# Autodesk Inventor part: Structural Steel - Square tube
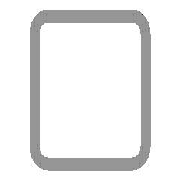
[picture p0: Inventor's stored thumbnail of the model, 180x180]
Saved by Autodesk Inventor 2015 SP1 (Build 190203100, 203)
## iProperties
_CCFamilyMember: 2
_CCFamilyDisplayName: ISO 4019 (Square) - Structural steels - Cold-formed, welded, structural hollow sections
_FrameMemberDoc: Frame Member File
_Version: 15.0.0
_GetPNFromCC: 1
Created: 2011-02
Part Number: Structural Steel - Square tube
Material: Stainless Steel
Document SubType Name: Modeling
Standard: ISO
Designer: Guilherme Augusto Franco de Souza
Standard Revision: Second edition 2001-09-01
Standards Organization: ISO
Language: en-US
Size Designation: 25x25x2
Categories: <MemberInstance><Categories><Category DisplayName="Structural Shapes" InternalName="089c4875-fa83-4c05-b084-43b9cc11f5ed" Mnemonic="GRDR"><CategoryParameter Dis
Stock Number: 25x25x2
Density: 8.08 g/cm^3
Description: ISO 4019 - 25x25x2
Appearance: Steel
G_L: 225,000 mm
G_W: 25,000 mm
G_H: 25,000 mm
+F6DD3AC6-5505-4A6A-B595-A047C3CF548A+CUTDETAIL1: Miter 45,00 deg
+88C288E7-B67C-452E-8AA9-2F07C8F866CF+CUTDETAIL2: Cut
IsCustomPart: 1
Author: Guilherme Augusto Franco de Souza
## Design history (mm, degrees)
node "Start plane"
node "End plane"
sketch "Sketch"
  geometry: L1 (-12.5, -8.5)-(-12.5, 8.5); L2 (-8.5, 12.5)-(8.5, 12.5); L3 (12.5, 8.5)-(12.5, -8.5); L4 (8.5, -12.5)-(-8.5, -12.5); L5 (-8.5, 10.5)-(8.5, 10.5); L6 (10.5, 8.5)-(10.5, -8.5); L7 (8.5, -10.5)-(-8.5, -10.5); L8 (-10.5, -8.5)-(-10.5, 8.5); L9 (0, 18.66)-(0, -18.66) reference; L10 (-18.66, 0)-(18.66, 0) reference; A1 r 4 centre (-8.5, -8.5) between (-12.5, -8.5) and (-8.5, -12.5); A2 r 4 centre (8.5, 8.5) between (12.5, 8.5) and (8.5, 12.5); A3 r 4 centre (-8.5, 8.5) between (-8.5, 12.5) and (-12.5, 8.5); A4 r 4 centre (8.5, -8.5) between (8.5, -12.5) and (12.5, -8.5); A5 r 2 centre (-8.5, 8.5) between (-8.5, 10.5) and (-10.5, 8.5); A6 r 2 centre (8.5, 8.5) between (10.5, 8.5) and (8.5, 10.5); A7 r 2 centre (8.5, -8.5) between (8.5, -10.5) and (10.5, -8.5); A8 r 2 centre (-8.5, -8.5) between (-10.5, -8.5) and (-8.5, -10.5)
  constraints: 16 end point, 16 point on circle, 8 centre point, 8 tangent, 4 parallel, 3 equal radius, 2 perpendicular, 7 other
  dimensions: "d7" = 4 radius of A1 (= G_IR); "d9" = 25 distance between parallel lines of L1 L3 (= G_W); "d11" = 25 distance between parallel lines of L2 L4 (= G_H); "d12" = 2 distance between parallel lines of L3 L6 (= G_T); "d15" = 12.5 distance between parallel lines of L9 L3 (= 0.5 x d9); "d16" = 12.5 distance between parallel lines of L2 L10 (= 0.5 x d11)
extrude "Body" new body sketch "Sketch" stored distance "d3" = 225 (= G_L); taper "d4" = 0 deg
node "Driven Length"
  sketch "Sketch3"
    geometry: L1 (0, 0)-(10, 0) reference
    constraints: 2 end point, 1 horizontal
  workplane "Work Plane3"
  sketch "Sketch4"
    geometry: L1 (-2, 0.141)-(12, 0.141) reference; L2 (-2, 200)-(12, 200) reference
    dimensions: "d18" = 199.85858 distance between parallel lines of L1 L2 (derived)
workplane "Work Plane4"
split "Split1"
workplane "Work Plane5"
split "Split2"
node "Hole2"
node "Hole4"
body "Solid1"
sketch "Sketch5"
  geometry: 4 further points
hole "Hole1" sketch "Sketch5" diameter "d19" = 6.6; stored, may be unused: countersink angle "d23" = 90 deg, drill point angle "d25" = 0 deg; dims "d20" = 6, "d21" = 4, "d22" = 2, "d24" = 8
sketch "Sketch6"
  geometry: 4 further points
hole "Hole3" sketch "Sketch6" diameter "d26" = 6.6; stored, may be unused: countersink angle "d30" = 90 deg, drill point angle "d32" = 0 deg; dims "d27" = 6, "d28" = 4, "d29" = 2, "d31" = 8
other parameters: "G_W" = 25 [user parameter; used in 1 equation term], "G_H" = 25 [user parameter; used in 1 equation term], "G_T" = 2 [user parameter; used in 1 equation term], "G_IR" = 4 [user parameter; used in 1 equation term], "G_L" = 225 [user parameter; used in 1 equation term], "G_OFFSET_START" = -0.14142 [user parameter; used in 1 equation term], "G_OFFSET_END" = -25 [user parameter; used in 1 equation term], "d13" = 0.14142 (= -G_OFFSET_START), "d14" = 200 (= G_OFFSET_END + B_L), "B_L" = 225 [user parameter; used in 1 equation term], "d17" = 90 deg, "MAS" = 0.136 [user parameter]
